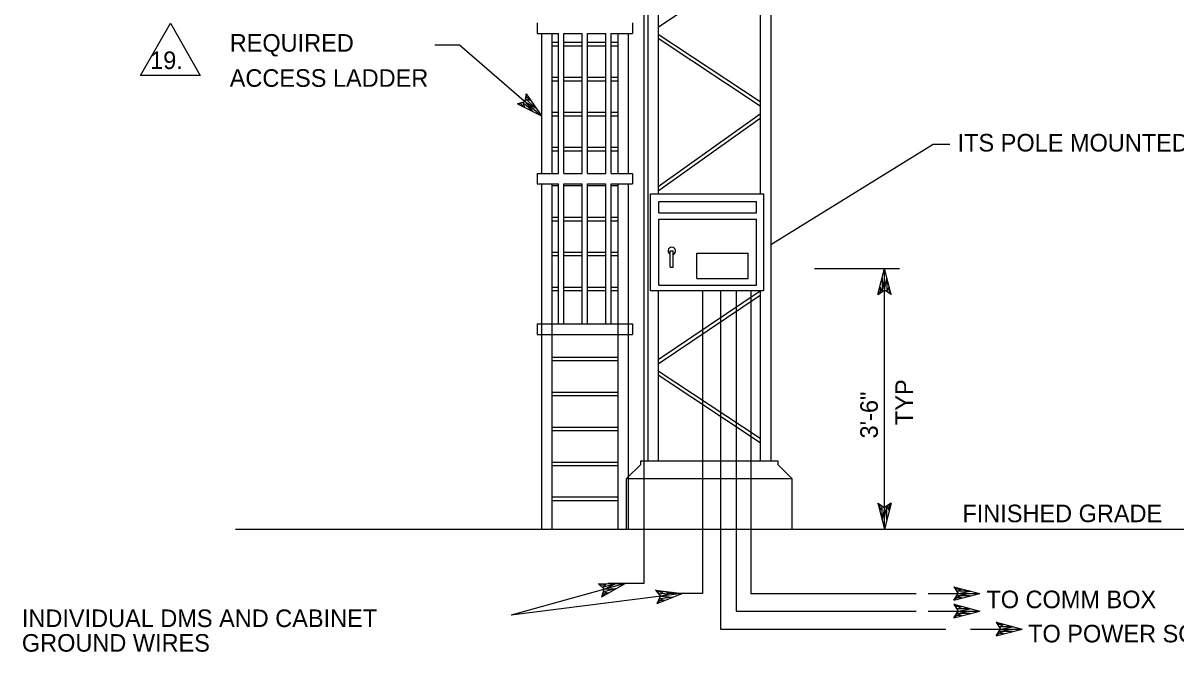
# Model space of a CAD drawing. Extents: x 515543 to 517243, y 661761 to 662861.
# Drawn here: x 516716.7 to 517056.7, y 661956.7 to 662142.1 of the extents above; entities that cross this region are included whole.
import ezdxf

# ---------------------------------------------------------------- set-up
doc = ezdxf.new("R2010")
doc.units = 0
for name, color, linetype in [('Level 8', 7, 'Continuous'), ('LTT', 7, 'Continuous'), ('SHT-BNDRY', 7, 'Continuous')]:
    doc.layers.add(name, color=color, linetype=linetype)

msp = doc.modelspace()

# ---------------------------------------------------------------- linework, layer by layer
at = {"layer": 'Level 8'}
for p, q in [((516904.01, 662276.09), (516904.01, 662091.76)), ((516937.19, 662276.09), (516937.19, 662013.03)), ((516899.74, 662196.46), (516899.74, 661976.89)), ((516904.01, 662140.94), (516934.08, 662161.17)), ((516868.34, 662142.18), (516868.34, 662139.07)), ((516896.39, 662142.18), (516896.39, 662139.07)), ((516896.39, 662142.18), (516896.39, 662139.07)), ((516868.34, 662139.07), (516874.57, 662139.07)), ((516869.55, 662139.07), (516869.55, 662097.82)), ((516872.66, 662139.07), (516872.66, 662097.82)), ((516874.57, 662097.82), (516874.57, 662139.07)), ((516876.13, 662139.07), (516881.59, 662139.07)), ((516876.13, 662097.82), (516876.13, 662139.07)), ((516881.59, 662097.82), (516881.59, 662139.07)), ((516883.14, 662139.07), (516888.6, 662139.07)), ((516883.14, 662097.82), (516883.14, 662139.07)), ((516888.6, 662097.82), (516888.6, 662139.07)), ((516890.15, 662139.07), (516896.39, 662139.07)), ((516890.15, 662097.82), (516890.15, 662139.07)), ((516892.06, 662139.07), (516892.06, 662097.82)), ((516895.17, 662139.07), (516895.17, 662097.82)), ((516904.01, 662138.9), (516934.08, 662118.99)), ((516872.66, 662136.48), (516874.57, 662136.48)), ((516872.66, 662135.44), (516874.57, 662135.44)), ((516876.13, 662136.48), (516881.59, 662136.48)), ((516876.13, 662135.44), (516881.59, 662135.44)), ((516883.14, 662136.48), (516888.6, 662136.48)), ((516883.14, 662135.44), (516888.6, 662135.44)), ((516890.15, 662136.48), (516892.06, 662136.48)), ((516890.15, 662135.44), (516892.06, 662135.44)), ((516904.01, 662137.66), (516934.08, 662117.75)), ((516872.66, 662126.16), (516874.57, 662126.16)), ((516872.66, 662125.13), (516874.57, 662125.13)), ((516876.13, 662126.16), (516881.59, 662126.16)), ((516876.13, 662125.13), (516881.59, 662125.13)), ((516883.14, 662126.16), (516888.6, 662126.16)), ((516883.14, 662125.13), (516888.6, 662125.13)), ((516890.15, 662126.16), (516892.06, 662126.16)), ((516890.15, 662125.13), (516892.06, 662125.13)), ((516872.66, 662115.85), (516874.57, 662115.85)), ((516872.66, 662114.81), (516874.57, 662114.81)), ((516876.13, 662115.85), (516881.59, 662115.85)), ((516876.13, 662114.81), (516881.59, 662114.81)), ((516883.14, 662115.85), (516888.6, 662115.85)), ((516883.14, 662114.81), (516888.6, 662114.81)), ((516890.15, 662115.85), (516892.06, 662115.85)), ((516890.15, 662114.81), (516892.06, 662114.81)), ((516934.08, 662115.27), (516904.01, 662093.83)), ((516934.08, 662114), (516904.01, 662092.56)), ((516872.66, 662105.54), (516874.57, 662105.54)), ((516872.66, 662104.5), (516874.57, 662104.5)), ((516876.13, 662105.54), (516881.59, 662105.54)), ((516876.13, 662104.5), (516881.59, 662104.5)), ((516883.14, 662105.54), (516888.6, 662105.54)), ((516883.14, 662104.5), (516888.6, 662104.5)), ((516890.15, 662105.54), (516892.06, 662105.54)), ((516890.15, 662104.5), (516892.06, 662104.5)), ((516868.34, 662097.82), (516868.34, 662094.71)), ((516868.34, 662097.82), (516874.57, 662097.82)), ((516876.13, 662097.82), (516881.59, 662097.82)), ((516883.14, 662097.82), (516888.6, 662097.82)), ((516890.15, 662097.82), (516896.39, 662097.82)), ((516896.39, 662097.82), (516896.39, 662094.71)), ((516896.39, 662097.82), (516896.39, 662094.71)), ((516868.34, 662094.71), (516874.57, 662094.71)), ((516869.55, 662094.71), (516869.55, 661992.93)), ((516872.66, 662094.71), (516872.66, 661992.93)), ((516872.66, 662094.19), (516874.57, 662094.19)), ((516874.57, 662053.45), (516874.57, 662094.71)), ((516876.13, 662094.71), (516881.59, 662094.71)), ((516876.13, 662053.45), (516876.13, 662094.71)), ((516876.13, 662094.19), (516881.59, 662094.19)), ((516881.59, 662053.45), (516881.59, 662094.71)), ((516883.14, 662094.71), (516888.6, 662094.71)), ((516883.14, 662053.45), (516883.14, 662094.71)), ((516883.14, 662094.19), (516888.6, 662094.19)), ((516888.6, 662053.45), (516888.6, 662094.71)), ((516890.15, 662094.71), (516896.39, 662094.71)), ((516890.15, 662053.45), (516890.15, 662094.71)), ((516890.15, 662094.19), (516892.06, 662094.19)), ((516892.06, 662094.71), (516892.06, 661992.93)), ((516895.17, 662094.71), (516895.17, 661992.93)), ((516901.71, 662091.76), (516935.08, 662091.76)), ((516901.71, 662063.15), (516901.71, 662091.76)), ((516935.08, 662091.76), (516935.08, 662063.15)), ((516904.22, 662089.51), (516932.96, 662089.51)), ((516904.22, 662086.2), (516904.22, 662089.51)), ((516932.96, 662086.2), (516932.96, 662089.51)), ((516872.66, 662084.91), (516874.57, 662084.91)), ((516876.13, 662084.91), (516881.59, 662084.91)), ((516883.14, 662084.91), (516888.6, 662084.91)), ((516890.15, 662084.91), (516892.06, 662084.91)), ((516904.22, 662086.2), (516932.96, 662086.2)), ((516904.22, 662084.34), (516932.96, 662084.34)), ((516904.22, 662064.88), (516904.22, 662084.34)), ((516932.96, 662064.88), (516932.96, 662084.34)), ((516872.66, 662083.87), (516874.57, 662083.87)), ((516876.13, 662083.87), (516881.59, 662083.87)), ((516883.14, 662083.87), (516888.6, 662083.87)), ((516890.15, 662083.87), (516892.06, 662083.87)), ((516872.66, 662074.6), (516874.57, 662074.6)), ((516876.13, 662074.6), (516881.59, 662074.6)), ((516883.14, 662074.6), (516888.6, 662074.6)), ((516890.15, 662074.6), (516892.06, 662074.6)), ((516907.53, 662070.17), (516907.53, 662074.94)), ((516907.53, 662074.94), (516908.46, 662074.94)), ((516908.46, 662070.17), (516908.46, 662074.94)), ((516915.35, 662074.28), (516930.58, 662074.28)), ((516915.35, 662066.86), (516915.35, 662074.28)), ((516930.58, 662066.86), (516930.58, 662074.28)), ((516872.66, 662073.56), (516874.57, 662073.56)), ((516876.13, 662073.56), (516881.59, 662073.56)), ((516883.14, 662073.56), (516888.6, 662073.56)), ((516890.15, 662073.56), (516892.06, 662073.56)), ((516907.53, 662070.17), (516908.46, 662070.17)), ((516950.06, 662069.75), (516975.14, 662069.75)), ((516970.76, 661992.93), (516970.76, 662069.75)), ((516872.66, 662064.28), (516874.57, 662064.28)), ((516876.13, 662064.28), (516881.59, 662064.28)), ((516883.14, 662064.28), (516888.6, 662064.28)), ((516890.15, 662064.28), (516892.06, 662064.28)), ((516904.22, 662064.88), (516932.96, 662064.88)), ((516915.35, 662066.86), (516930.58, 662066.86)), ((516872.66, 662063.25), (516874.57, 662063.25)), ((516876.13, 662063.25), (516881.59, 662063.25)), ((516883.14, 662063.25), (516888.6, 662063.25)), ((516890.15, 662063.25), (516892.06, 662063.25)), ((516935.08, 662063.15), (516901.71, 662063.15)), ((516904.01, 662042.94), (516934.08, 662063.16)), ((516904.01, 662063.15), (516904.01, 662013.03)), ((516904.01, 662041.69), (516934.08, 662061.91)), ((516917.06, 662063.15), (516917.06, 661973.94)), ((516868.34, 662053.45), (516896.39, 662053.45)), ((516868.34, 662053.45), (516868.34, 662050.34)), ((516896.39, 662053.45), (516896.39, 662050.34)), ((516896.39, 662053.45), (516896.39, 662050.34)), ((516868.34, 662050.34), (516896.39, 662050.34)), ((516872.66, 662043.66), (516892.06, 662043.66)), ((516872.66, 662042.62), (516892.06, 662042.62)), ((516904.01, 662039.65), (516934.08, 662019.74)), ((516904.01, 662038.41), (516934.08, 662018.5)), ((516872.66, 662033.35), (516892.06, 662033.35)), ((516872.66, 662032.31), (516892.06, 662032.31)), ((516872.66, 662023.03), (516892.06, 662023.03)), ((516872.66, 662022), (516892.06, 662022)), ((516872.66, 662012.72), (516892.06, 662012.72)), ((516872.66, 662011.68), (516892.06, 662011.68)), ((516894.68, 662007.85), (516943.41, 662007.85)), ((516872.66, 662002.41), (516892.06, 662002.41)), ((516872.66, 662001.37), (516892.06, 662001.37)), ((516779.3, 661992.93), (517064.88, 661992.93)), ((516894.26, 661976.89), (516860.65, 661967.6)), ((516899.74, 661976.89), (516889.19, 661976.89)), ((516911.06, 661973.94), (516860.65, 661967.6)), ((516917.06, 661973.94), (516906.5, 661973.94))]:
    msp.add_line(p, q, dxfattribs=at)
for points in [[(516904.01, 662276.09), (516900.9, 662276.09), (516900.9, 662013.03)], [(516937.19, 662276.09), (516934.08, 662276.09), (516934.08, 662091.76)], [(516838.15, 662135.74), (516845.36, 662135.74), (516869.55, 662114.78)], [(516937.19, 662076.8), (516985.13, 662106.45), (516989.99, 662106.45)], [(516922.33, 662063.15), (516922.33, 661963.47), (516988.87, 661963.47)], [(516927.03, 662063.15), (516927.03, 661968.78), (516980.03, 661968.78)], [(516931.35, 662063.15), (516931.35, 661973.94), (516980.03, 661973.94)], [(516934.08, 662063.15), (516934.08, 662013.03)], [(516894.68, 661992.93), (516894.68, 662007.85), (516898.83, 662011.99), (516898.83, 662013.03), (516939.26, 662013.03), (516939.26, 662011.99), (516943.41, 662007.85), (516943.41, 661992.93)]]:
    msp.add_lwpolyline(points, dxfattribs=at)
msp.add_arc((516908, 662074.94), 1.11, 294.6133, 245.3867, dxfattribs=at)
at = {"layer": 'LTT'}
for p, q in [((516983.63, 661973.94), (516998.88, 661973.94)), ((516983.63, 661968.78), (516998.88, 661968.78)), ((516996.06, 661963.47), (517011.31, 661963.47))]:
    msp.add_line(p, q, dxfattribs=at)
for points in [[(516864.81, 662118.89), (516866.94, 662116.14), (516864.03, 662118.66), (516864.56, 662117.38), (516863.57, 662118.23), (516862.47, 662118.29), (516864.71, 662118.98)], [(516862.47, 662118.29), (516869.55, 662114.78)], [(516864.81, 662118.89), (516867.84, 662117.17), (516864.92, 662119.7), (516866.27, 662119.35), (516865.29, 662120.21), (516865.08, 662121.3), (516864.71, 662118.98)], [(516865.08, 662121.3), (516869.55, 662114.78)], [(516968.77, 662062.1), (516970.76, 662069.75)], [(516972.75, 662062.1), (516970.76, 662069.75)], [(516970.76, 662063.47), (516970.08, 662066.89), (516970.08, 662063.03), (516969.46, 662064.28), (516969.46, 662062.97), (516968.77, 662062.1), (516970.76, 662063.34)], [(516970.76, 662063.47), (516971.45, 662066.89), (516971.45, 662063.03), (516972.07, 662064.28), (516972.07, 662062.97), (516972.75, 662062.1), (516970.76, 662063.34)], [(516970.76, 661999.21), (516970.08, 661995.79), (516970.08, 661999.64), (516969.46, 661998.4), (516969.46, 661999.71), (516968.77, 662000.58), (516970.76, 661999.33)], [(516968.77, 662000.58), (516970.76, 661992.93)], [(516970.76, 661999.21), (516971.45, 661995.79), (516971.45, 661999.64), (516972.07, 661998.4), (516972.07, 661999.71), (516972.75, 662000.58), (516970.76, 661999.33)], [(516972.75, 662000.58), (516970.76, 661992.93)], [(516886.35, 661976.77), (516894.26, 661976.89)], [(516888.2, 661975.22), (516891.32, 661976.79), (516887.6, 661975.76), (516888.63, 661976.69), (516887.37, 661976.35), (516886.35, 661976.77), (516888.08, 661975.19)], [(516887.41, 661972.94), (516894.26, 661976.89)], [(516888.2, 661975.22), (516891.68, 661975.47), (516887.96, 661974.44), (516889.33, 661974.18), (516888.07, 661973.83), (516887.41, 661972.94), (516888.08, 661975.19)], [(516992.59, 661973.94), (516996.02, 661974.63), (516992.16, 661974.63), (516993.4, 661975.25), (516992.1, 661975.25), (516991.23, 661975.93), (516992.47, 661973.94)], [(516991.23, 661975.93), (516998.88, 661973.94)], [(516904.82, 661973.16), (516908.13, 661974.26), (516904.31, 661973.78), (516905.46, 661974.55), (516904.17, 661974.39), (516903.22, 661974.96), (516904.7, 661973.14)], [(516903.22, 661974.96), (516911.06, 661973.94)], [(516904.82, 661973.16), (516908.13, 661974.26), (516904.31, 661973.78), (516905.46, 661974.55), (516904.17, 661974.39), (516903.22, 661974.96), (516904.7, 661973.14)], [(516903.22, 661974.96), (516911.06, 661973.94)], [(516903.71, 661971.01), (516911.06, 661973.94)], [(516903.71, 661971.01), (516911.06, 661973.94)], [(516904.82, 661973.16), (516908.3, 661972.91), (516904.48, 661972.42), (516905.79, 661971.96), (516904.49, 661971.8), (516903.71, 661971.01), (516904.7, 661973.14)], [(516904.82, 661973.16), (516908.3, 661972.91), (516904.48, 661972.42), (516905.79, 661971.96), (516904.49, 661971.8), (516903.71, 661971.01), (516904.7, 661973.14)], [(516992.59, 661973.94), (516996.02, 661973.26), (516992.16, 661973.26), (516993.4, 661972.64), (516992.1, 661972.64), (516991.23, 661971.95), (516992.47, 661973.94)], [(516991.23, 661971.95), (516998.88, 661973.94)], [(516992.59, 661968.78), (516996.02, 661969.46), (516992.16, 661969.46), (516993.4, 661970.09), (516992.1, 661970.09), (516991.23, 661970.77), (516992.47, 661968.78)], [(516991.23, 661970.77), (516998.88, 661968.78)], [(516992.59, 661968.78), (516996.02, 661968.09), (516992.16, 661968.09), (516993.4, 661967.47), (516992.1, 661967.47), (516991.23, 661966.79), (516992.47, 661968.78)], [(516991.23, 661966.79), (516998.88, 661968.78)], [(517005.03, 661963.47), (517008.45, 661964.16), (517004.59, 661964.16), (517005.84, 661964.78), (517004.53, 661964.78), (517003.66, 661965.46), (517004.9, 661963.47)], [(517003.66, 661965.46), (517011.31, 661963.47)], [(517005.03, 661963.47), (517008.45, 661962.79), (517004.59, 661962.79), (517005.84, 661962.17), (517004.53, 661962.17), (517003.66, 661961.48), (517004.9, 661963.47)], [(517003.66, 661961.48), (517011.31, 661963.47)]]:
    msp.add_lwpolyline(points, dxfattribs=at)
at = {"layer": 'SHT-BNDRY'}
msp.add_lwpolyline([(516751.3, 662126.65), (516760.2, 662142.07), (516768.92, 662126.65)], close=True, dxfattribs=at)

# ---------------------------------------------------------------- texts
at = {"layer": 'Level 8'}
for s, rotation, p in [('REQUIRED', 360, (516777.64, 662133.69)), ('19.', 360, (516754.17, 662128.57)), ('ACCESS LADDER', 360, (516777.64, 662123.33)), ('ITS POLE MOUNTED CABINET', 360, (516992.3, 662104.26)), ('TYP', 90, (516979.14, 662023.62)), ('3\'-6"', 90, (516968.77, 662019.66)), ('FINISHED GRADE', 360, (516993.71, 661994.98)), ('TO COMM BOX', 360, (517000.79, 661969.63))]:
    msp.add_text(s, height=5.184, rotation=rotation, dxfattribs=at).set_placement(p)
for s, p in [('INDIVIDUAL DMS AND CABINET', (516716.34, 661964.06)), ('GROUND WIRES', (516716.34, 661956.81)), ('TO POWER SOURCE', (517013.09, 661959.54))]:
    msp.add_text(s, height=5.184, dxfattribs=at).set_placement(p)

doc.saveas('drawing.dxf')
